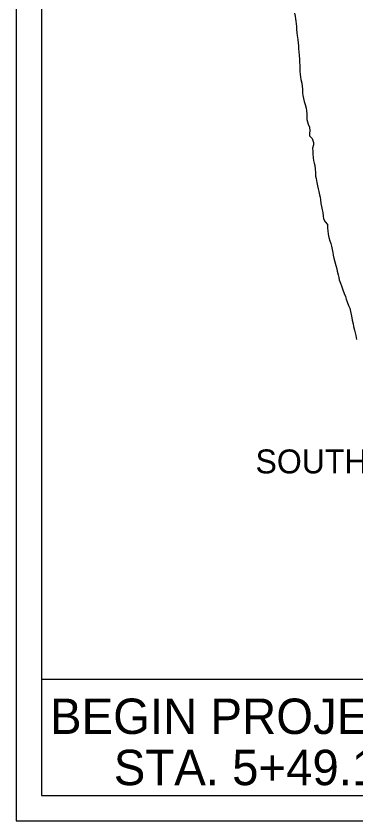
# Model space of a CAD drawing. Extents: x 0 to 45.4, y -2.2 to 22.
# Drawn here: x 2 to 3.344, y 14 to 17.183 of the extents above; entities that cross this region are included whole.
import ezdxf

# ---------------------------------------------------------------- set-up
doc = ezdxf.new("R2010")
doc.units = 0
for name, color, linetype in [('GM_X_Corporation_Text', 7, 'Continuous'), ('GM_X_Major_River', 7, 'Continuous'), ('SH_Data', 7, 'Continuous'), ('SH_Text', 7, 'Continuous')]:
    doc.layers.add(name, color=color, linetype=linetype)

msp = doc.modelspace()

# ---------------------------------------------------------------- linework, layer by layer
at = {"layer": 'GM_X_Major_River'}
for points in [[(3.1015, 17.195), (3.1034, 17.1824), (3.1049, 17.1722), (3.1064, 17.1627), (3.1075, 17.1524), (3.1083, 17.1422), (3.109, 17.1315), (3.1106, 17.1167), (3.1121, 17.1061), (3.1136, 17.0905), (3.1151, 17.0765), (3.1162, 17.0666), (3.1174, 17.0533), (3.1177, 17.043), (3.1192, 17.0267), (3.1204, 17.0126), (3.1211, 17.0005), (3.1219, 16.988), (3.1219, 16.9773), (3.1226, 16.9648), (3.1238, 16.9522), (3.1241, 16.9424), (3.1257, 16.9317), (3.1298, 16.9184), (3.1317, 16.9063), (3.1328, 16.8945), (3.1332, 16.8797), (3.134, 16.8694), (3.1359, 16.8573), (3.1396, 16.8451), (3.1434, 16.8333), (3.1468, 16.8192), (3.1479, 16.809), (3.1491, 16.7968), (3.1495, 16.7873), (3.1498, 16.7744), (3.1525, 16.7649), (3.1555, 16.755)], [(3.1555, 16.755), (3.16, 16.7436), (3.1615, 16.7299), (3.16, 16.7197), (3.1608, 16.709), (3.1706, 16.6988), (3.1763, 16.6832), (3.1755, 16.6733), (3.1717, 16.6608), (3.1733, 16.6475), (3.174, 16.638), (3.1751, 16.6231), (3.1767, 16.6125), (3.1793, 16.6015), (3.1812, 16.592), (3.1827, 16.5779), (3.1835, 16.565), (3.1846, 16.5505), (3.1865, 16.5406), (3.1891, 16.5247), (3.1925, 16.5114), (3.1948, 16.4996), (3.1974, 16.4889), (3.1997, 16.4764), (3.202, 16.4665), (3.2035, 16.4566), (3.2057, 16.4422), (3.208, 16.4304), (3.2107, 16.4171), (3.2133, 16.4061), (3.2137, 16.3924), (3.2152, 16.3813), (3.2224, 16.3699), (3.2311, 16.3582), (3.2318, 16.3448), (3.2322, 16.3338), (3.2341, 16.3201), (3.2371, 16.3068), (3.2409, 16.2947), (3.2447, 16.2833), (3.2473, 16.273), (3.25, 16.2604), (3.2519, 16.2487), (3.2541, 16.2373), (3.2571, 16.2251), (3.2605, 16.2106), (3.2647, 16.1962), (3.2681, 16.1837), (3.2696, 16.1742), (3.273, 16.1597), (3.2757, 16.1498), (3.2776, 16.1399), (3.2825, 16.1274), (3.2866, 16.116), (3.2919, 16.1008), (3.2976, 16.0863), (3.3025, 16.0742), (3.3051, 16.0635), (3.3093, 16.0525), (3.3146, 16.0388), (3.3191, 16.0274), (3.3225, 16.0153), (3.3244, 16.0035), (3.3271, 15.9902), (3.3293, 15.9807), (3.3324, 15.9662), (3.3346, 15.956), (3.3384, 15.9412), (3.3407, 15.9305), (3.3429, 15.9199), (3.3463, 15.9035)]]:
    msp.add_lwpolyline(points, dxfattribs=at)
at = {"layer": 'SH_Data'}
for p, q in [((2, 21), (2, 14)), ((2.1, 20.9), (2.1, 14.1)), ((2.1, 14.1), (8.9, 14.1)), ((2.1, 14.1), (2.1, 14.1)), ((2, 14), (9, 14))]:
    msp.add_line(p, q, dxfattribs=at)
at = {"layer": 'SH_Text'}
msp.add_lwpolyline([(3.5871, 14.5594), (2.1, 14.5594), (2.1, 14.1), (3.5871, 14.1)], close=True, dxfattribs=at)

# ---------------------------------------------------------------- texts
at = {"layer": 'GM_X_Corporation_Text'}
msp.add_text('SOUTH POINT', height=0.094697, rotation=0, dxfattribs=at).set_placement((2.9467, 15.3744))
at = {"layer": 'SH_Text'}
for s, p in [('BEGIN PROJECT', (2.1341, 14.3438)), ('STA. 5+49.10', (2.3862, 14.1413))]:
    msp.add_text(s, height=0.14, dxfattribs=at).set_placement(p)

doc.saveas('drawing.dxf')
